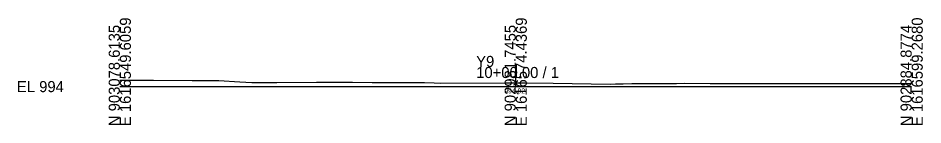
# Model space of a CAD drawing. Extents: x -26 to 1403, y -10 to 3021.
# Drawn here: x -25.7 to 202.8, y -9.7 to 17.3 of the extents above; entities that cross this region are included whole.
import ezdxf

# ---------------------------------------------------------------- set-up
doc = ezdxf.new("R2010")
doc.units = 0
for name, color, linetype in [('Exist Cross Section Cell', 7, 'Continuous'), ('Exist XS Center Line Elevation Label', 7, 'Continuous'), ('Exist XS Ground Line', 7, 'Continuous')]:
    doc.layers.add(name, color=color, linetype=linetype)

msp = doc.modelspace()

# ---------------------------------------------------------------- linework, layer by layer
at = {"layer": 'Exist Cross Section Cell'}
for p, q in [((100, 0), (100, 4.97)), ((0, 0), (100, 0)), ((100, 0), (200, 0))]:
    msp.add_line(p, q, dxfattribs=at)
at = {"layer": 'Exist XS Ground Line'}
for p, q in [((0, 1.66), (8.54, 1.63)), ((8.54, 1.63), (18.24, 1.58)), ((18.24, 1.58), (19.54, 1.58)), ((19.54, 1.58), (25, 1.56)), ((25, 1.56), (30.35, 1.23)), ((30.35, 1.23), (33.38, 1.06)), ((33.38, 1.06), (39.69, 1.07)), ((39.69, 1.07), (49.68, 1.09)), ((49.68, 1.09), (50.87, 1.09)), ((50.87, 1.09), (53.71, 1.1)), ((53.71, 1.1), (58.74, 1.1)), ((58.74, 1.1), (63.72, 1.08)), ((63.72, 1.08), (68.07, 1.06)), ((68.07, 1.06), (71.51, 1.06)), ((71.51, 1.06), (73.84, 1.05)), ((73.84, 1.05), (76.94, 1)), ((76.94, 1), (79.37, 0.93)), ((79.37, 0.93), (81.09, 0.85)), ((81.09, 0.85), (97.12, 0.92)), ((97.12, 0.92), (100, 0.92)), ((100, 0.92), (102.89, 0.92)), ((102.89, 0.92), (109.46, 0.9)), ((109.46, 0.9), (123.82, 0.65)), ((123.82, 0.65), (125.2, 0.68)), ((125.2, 0.68), (127.11, 0.73)), ((127.11, 0.73), (129.32, 0.79)), ((129.32, 0.79), (138.77, 0.76)), ((138.77, 0.76), (140.58, 0.8)), ((140.58, 0.8), (142.57, 0.85)), ((142.57, 0.85), (149.1, 0.82)), ((149.1, 0.82), (162.1, 0.82)), ((162.1, 0.82), (169.39, 0.8)), ((169.39, 0.8), (177.39, 0.78)), ((177.39, 0.78), (187.28, 0.77)), ((187.28, 0.77), (195.8, 0.76)), ((195.8, 0.76), (200, 0.75))]:
    msp.add_line(p, q, dxfattribs=at)

# ---------------------------------------------------------------- texts
at = {"layer": 'Exist Cross Section Cell'}
for s, p in [('E 1616549.6059', (2.8, -10)), ('E 1616574.4369', (102.8, -10)), ('E 1616599.2680', (202.8, -10)), ('N 903078.6135', (0, -10)), ('N 902981.7455', (100, -10)), ('N 902884.8774', (200, -10))]:
    msp.add_text(s, height=2.8, rotation=90, dxfattribs=at).set_placement(p)
for s, p in [('Y9', (90, 4.97)), ('10+00.00 / 1', (90, 2.17)), ('EL 994', (-26, -1.4))]:
    msp.add_text(s, height=2.8, dxfattribs=at).set_placement(p)
at = {"layer": 'Exist XS Center Line Elevation Label'}
msp.add_text('994.92', height=1.25, dxfattribs=at).set_placement((97.1, -1.71))

doc.saveas('drawing.dxf')
